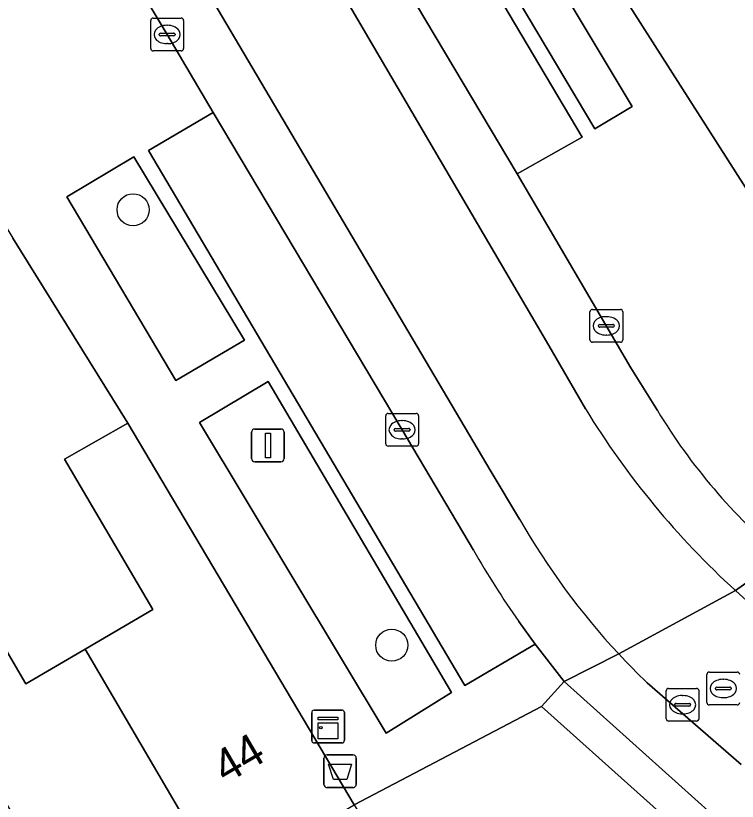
# Model space of a CAD drawing. Extents: x 161771 to 163125, y 382475 to 383179.
# Drawn here: x 162324.43 to 162346.44, y 382872.2 to 382896.16 of the extents above; entities that cross this region are included whole.
import ezdxf

# ---------------------------------------------------------------- set-up
doc = ezdxf.new("R2010")
doc.units = 0
for name, color, linetype in [('IMGEO_Afvalbak', 7, 'Continuous'), ('IMGEO_Boom', 7, 'Continuous'), ('IMGEO_Erf', 7, 'Continuous'), ('IMGEO_Groenvoorziening', 7, 'Continuous'), ('IMGEO_Kast', 7, 'Continuous'), ('IMGEO_Kolk', 7, 'Continuous'), ('IMGEO_Lichtmast', 7, 'Continuous'), ('IMGEO_Pand', 7, 'Continuous'), ('IMGEO_Pand_nummerreeks', 7, 'Continuous'), ('IMGEO_Parkeervlak_open', 7, 'Continuous'), ('IMGEO_Rijbaan_lokaal_gesloten', 7, 'Continuous'), ('IMGEO_Rioolput', 7, 'Continuous'), ('IMGEO_Voetpad_open', 7, 'Continuous')]:
    doc.layers.add(name, color=color, linetype=linetype)

msp = doc.modelspace()

# ---------------------------------------------------------------- linework, layer by layer
at = {"layer": 'IMGEO_Afvalbak'}
for p, q in [((162333.826, 382872.712), (162333.826, 382873.512)), ((162333.826, 382873.512), (162333.826, 382872.712)), ((162333.926, 382873.612), (162334.716, 382873.612)), ((162334.716, 382873.612), (162333.926, 382873.612)), ((162334.816, 382873.512), (162334.816, 382872.712)), ((162334.816, 382872.712), (162334.816, 382873.512)), ((162334.716, 382872.612), (162333.926, 382872.612)), ((162333.926, 382872.612), (162334.716, 382872.612))]:
    msp.add_line(p, q, dxfattribs=at)
msp.add_lwpolyline([(162333.969, 382873.326), (162334.673, 382873.326), (162334.524, 382872.856), (162334.118, 382872.856), (162333.969, 382873.326)], dxfattribs=at)
for centre, start, end in [((162333.926, 382873.512), 90, 180), ((162333.926, 382873.512), 90, 180), ((162334.716, 382873.512), 0, 90), ((162334.716, 382873.512), 360, 90), ((162333.926, 382872.712), 180, 270), ((162333.926, 382872.712), 180, 270), ((162334.716, 382872.712), 270, 0), ((162334.716, 382872.712), 270, 0)]:
    msp.add_arc(centre, 0.1, start, end, dxfattribs=at)
at = {"layer": 'IMGEO_Boom'}
for centre in [(162328.009, 382890.24), (162335.898, 382876.956)]:
    msp.add_circle(centre, 0.489, dxfattribs=at)
at = {"layer": 'IMGEO_Erf'}
for points in [[(162282.694, 382998.745), (162285.645, 382993.994), (162299.205, 382971.267), (162304.602, 382962.221), (162323.715, 382930.187), (162324.058, 382929.531), (162333.904, 382911.866), (162340.209, 382901.345), (162341.191, 382899.707), (162342.707, 382897.177), (162347.841, 382889.118), (162350.419, 382884.987), (162352.762, 382884.507), (162396.81, 382874.496)], [(162321.996, 382880.467), (162324.742, 382875.779), (162326.547, 382876.836), (162328.611, 382878.045), (162325.922, 382882.636), (162327.846, 382883.731), (162324.342, 382889.373)]]:
    msp.add_lwpolyline(points, dxfattribs=at)
at = {"layer": 'IMGEO_Groenvoorziening'}
for points in [[(162337.338, 382903.237), (162336.212, 382902.585), (162342.088, 382892.713), (162343.227, 382893.391)], [(162325.987, 382890.634), (162329.311, 382885.035), (162331.402, 382886.259), (162328.034, 382891.856)], [(162337.722, 382875.511), (162332.133, 382884.998), (162330.03, 382883.755), (162335.725, 382874.269)]]:
    msp.add_lwpolyline(points, close=True, dxfattribs=at)
at = {"layer": 'IMGEO_Kast'}
for p, q in [((162333.456, 382874.05), (162333.456, 382874.891)), ((162333.456, 382874.891), (162333.456, 382874.05)), ((162333.531, 382874.975), (162334.372, 382874.975)), ((162334.372, 382874.975), (162333.531, 382874.975)), ((162334.456, 382874.9), (162334.456, 382874.059)), ((162334.456, 382874.059), (162334.456, 382874.9)), ((162334.381, 382873.975), (162333.54, 382873.975)), ((162333.54, 382873.975), (162334.381, 382873.975))]:
    msp.add_line(p, q, dxfattribs=at)
for points in [[(162333.651, 382874.765), (162334.251, 382874.765), (162334.251, 382874.68), (162333.651, 382874.68), (162333.651, 382874.765)], [(162333.651, 382874.59), (162334.251, 382874.59), (162334.251, 382874.101), (162333.651, 382874.101), (162333.651, 382874.59)]]:
    msp.add_lwpolyline(points, dxfattribs=at)
msp.add_circle((162333.735, 382874.439), 0.0377, dxfattribs=at)
for centre, start, end in [((162333.534, 382874.897), 92.4484, 184.2845), ((162333.534, 382874.897), 92.4484, 184.2845), ((162334.378, 382874.897), 2.4484, 94.2845), ((162334.378, 382874.897), 2.4484, 94.2845), ((162333.534, 382874.053), 182.4484, 274.2845), ((162333.534, 382874.053), 182.4484, 274.2845), ((162334.378, 382874.053), 272.4484, 4.2845), ((162334.378, 382874.053), 272.4484, 4.2845)]:
    msp.add_arc(centre, 0.0779, start, end, dxfattribs=at)
at = {"layer": 'IMGEO_Kolk'}
for p, q in [((162328.547, 382895.161), (162328.547, 382896.013)), ((162328.622, 382896.087), (162329.474, 382896.087)), ((162329.548, 382896.013), (162329.548, 382895.161)), ((162329.035, 382895.867), (162329.06, 382895.867)), ((162328.806, 382895.581), (162328.806, 382895.593)), ((162329.244, 382895.544), (162328.846, 382895.544)), ((162328.849, 382895.63), (162329.247, 382895.63)), ((162329.29, 382895.593), (162329.29, 382895.581)), ((162329.058, 382895.307), (162329.033, 382895.307)), ((162329.474, 382895.087), (162328.622, 382895.087)), ((162341.943, 382886.273), (162341.943, 382887.125)), ((162342.018, 382887.199), (162342.87, 382887.199)), ((162342.944, 382887.125), (162342.944, 382886.273)), ((162342.431, 382886.979), (162342.456, 382886.979)), ((162342.202, 382886.693), (162342.202, 382886.705)), ((162342.64, 382886.656), (162342.242, 382886.656)), ((162342.245, 382886.742), (162342.643, 382886.742)), ((162342.686, 382886.705), (162342.686, 382886.693)), ((162342.454, 382886.419), (162342.429, 382886.419)), ((162342.87, 382886.199), (162342.018, 382886.199)), ((162335.789, 382884.028), (162336.641, 382884.028)), ((162335.714, 382883.102), (162335.714, 382883.954)), ((162336.202, 382883.808), (162336.227, 382883.808)), ((162336.715, 382883.954), (162336.715, 382883.102)), ((162335.973, 382883.522), (162335.973, 382883.534)), ((162336.016, 382883.571), (162336.414, 382883.571)), ((162336.457, 382883.534), (162336.457, 382883.522)), ((162336.411, 382883.485), (162336.013, 382883.485)), ((162336.641, 382883.028), (162335.789, 382883.028)), ((162336.225, 382883.248), (162336.2, 382883.248))]:
    msp.add_line(p, q, dxfattribs=at)
for points in [[(162328.547, 382895.161), (162328.547, 382896.013)], [(162328.622, 382896.087), (162329.474, 382896.087)], [(162329.548, 382896.013), (162329.548, 382895.161)], [(162329.474, 382895.087), (162328.622, 382895.087)], [(162341.943, 382886.273), (162341.943, 382887.125)], [(162342.018, 382887.199), (162342.87, 382887.199)], [(162342.944, 382887.125), (162342.944, 382886.273)], [(162342.87, 382886.199), (162342.018, 382886.199)], [(162335.789, 382884.028), (162336.641, 382884.028)], [(162335.714, 382883.102), (162335.714, 382883.954)], [(162336.715, 382883.954), (162336.715, 382883.102)], [(162336.641, 382883.028), (162335.789, 382883.028)]]:
    msp.add_lwpolyline(points, dxfattribs=at)
for centre, radius, start, end in [((162328.624, 382896.011), 0.0765, 91.552, 178.448), ((162328.624, 382896.011), 0.0765, 91.552, 178.448), ((162329.472, 382896.011), 0.0765, 1.552, 88.448), ((162329.472, 382896.011), 0.0765, 1.552, 88.448), ((162328.846, 382895.59), 0.0403, 85.8775, 175.7526), ((162328.843, 382895.58), 0.0366, 178.938, 274.7102), ((162329.247, 382895.587), 0.043, 264.8664, 352.4533), ((162329.251, 382895.592), 0.0386, 1.7309, 96.639), ((162328.624, 382895.163), 0.0765, 181.552, 268.448), ((162328.624, 382895.163), 0.0765, 181.552, 268.448), ((162329.472, 382895.163), 0.0765, 271.552, 358.448), ((162329.472, 382895.163), 0.0765, 271.552, 358.448), ((162342.02, 382887.123), 0.0765, 91.552, 178.448), ((162342.02, 382887.123), 0.0765, 91.552, 178.448), ((162342.868, 382887.123), 0.0765, 1.552, 88.448), ((162342.868, 382887.123), 0.0765, 1.552, 88.448), ((162342.242, 382886.702), 0.0403, 85.8775, 175.7526), ((162342.239, 382886.692), 0.0366, 178.938, 274.7102), ((162342.643, 382886.699), 0.043, 264.8664, 352.4533), ((162342.647, 382886.704), 0.0386, 1.7309, 96.639), ((162342.02, 382886.275), 0.0765, 181.552, 268.448), ((162342.02, 382886.275), 0.0765, 181.552, 268.448), ((162342.868, 382886.275), 0.0765, 271.552, 358.448), ((162342.868, 382886.275), 0.0765, 271.552, 358.448), ((162335.791, 382883.952), 0.0765, 91.552, 178.448), ((162335.791, 382883.952), 0.0765, 91.552, 178.448), ((162336.639, 382883.952), 0.0765, 1.552, 88.448), ((162336.639, 382883.952), 0.0765, 1.552, 88.448), ((162336.013, 382883.531), 0.0403, 85.8775, 175.7526), ((162336.01, 382883.521), 0.0366, 178.938, 274.7102), ((162336.414, 382883.528), 0.043, 264.8664, 352.4533), ((162336.418, 382883.533), 0.0386, 1.7309, 96.639), ((162335.791, 382883.104), 0.0765, 181.552, 268.448), ((162335.791, 382883.104), 0.0765, 181.552, 268.448), ((162336.639, 382883.104), 0.0765, 271.552, 358.448), ((162336.639, 382883.104), 0.0765, 271.552, 358.448)]:
    msp.add_arc(centre, radius, start, end, dxfattribs=at)
for centre, major_axis, ratio, start_param, end_param in [((162329.034, 382895.587), (-0.387, 0.002), 0.722429, 4.712389, 7.853982), ((162329.059, 382895.587), (-0.39, 0.002), 0.717154, 1.570796, 4.712389), ((162342.43, 382886.699), (-0.387, 0.002), 0.722429, 4.712389, 7.853982), ((162342.455, 382886.699), (-0.39, 0.002), 0.717154, 1.570796, 4.712389), ((162336.201, 382883.528), (-0.387, 0.002), 0.722429, 4.712389, 7.853982), ((162336.226, 382883.528), (-0.39, 0.002), 0.717154, 1.570796, 4.712389)]:
    msp.add_ellipse(centre, major_axis=major_axis, ratio=ratio, start_param=start_param, end_param=end_param, dxfattribs=at)
at = {"layer": 'IMGEO_Lichtmast'}
for p, q in [((162331.725, 382883.552), (162332.515, 382883.552)), ((162332.515, 382883.552), (162331.725, 382883.552)), ((162331.625, 382882.652), (162331.625, 382883.452)), ((162331.625, 382883.452), (162331.625, 382882.652)), ((162332.615, 382883.452), (162332.615, 382882.652)), ((162332.615, 382882.652), (162332.615, 382883.452)), ((162332.515, 382882.552), (162331.725, 382882.552)), ((162331.725, 382882.552), (162332.515, 382882.552))]:
    msp.add_line(p, q, dxfattribs=at)
msp.add_lwpolyline([(162332.045, 382883.427), (162332.195, 382883.427), (162332.195, 382882.677), (162332.045, 382882.677), (162332.045, 382883.427)], dxfattribs=at)
for centre, start, end in [((162331.725, 382883.452), 90, 180), ((162331.725, 382883.452), 90, 180), ((162332.515, 382883.452), 0, 90), ((162332.515, 382883.452), 360, 90), ((162331.725, 382882.652), 180, 270), ((162331.725, 382882.652), 180, 270), ((162332.515, 382882.652), 270, 0), ((162332.515, 382882.652), 270, 0)]:
    msp.add_arc(centre, 0.1, start, end, dxfattribs=at)
at = {"layer": 'IMGEO_Pand'}
for points in [[(162326.547, 382876.836), (162330.715, 382869.722), (162334.753, 382872.09), (162327.846, 382883.731), (162325.922, 382882.636), (162328.611, 382878.045)], [(162326.547, 382876.836), (162324.742, 382875.779), (162321.996, 382880.467), (162319.943, 382879.265), (162326.87, 382867.467), (162330.715, 382869.722)]]:
    msp.add_lwpolyline(points, close=True, dxfattribs=at)
at = {"layer": 'IMGEO_Parkeervlak_open'}
msp.add_lwpolyline([(162324.516, 382916.948), (162326.603, 382913.414), (162335.002, 382899.266), (162339.727, 382891.336), (162341.708, 382892.457), (162326.472, 382918.127)], close=True, dxfattribs=at)
for points in [[(162330.45, 382893.21), (162328.48, 382892.052), (162338.126, 382875.73), (162340.269, 382876.989), (162339.771, 382877.679)], [(162338.393, 382879.852), (162336.215, 382883.528), (162330.45, 382893.21)]]:
    msp.add_lwpolyline(points, dxfattribs=at)
msp.add_arc((162363.534, 382894.272), 28.983, 209.8365, 214.9249, dxfattribs=at)
at = {"layer": 'IMGEO_Rijbaan_lokaal_gesloten'}
for points in [[(162252.687, 383027.32), (162258.27, 383017.942), (162277.114, 382986.385), (162314.204, 382923.986), (162330.304, 382896.843), (162338.934, 382882.25), (162339.793, 382880.803)], [(162341.807, 382884.166), (162340.693, 382886.098), (162333.368, 382898.598), (162322.883, 382916.238), (162309.554, 382938.696), (162306.687, 382943.516), (162275.079, 382996.8)], [(162275.079, 382996.8), (162306.687, 382943.516), (162309.554, 382938.696), (162322.883, 382916.238), (162333.368, 382898.598), (162340.693, 382886.098), (162341.807, 382884.166)], [(162344.002, 382884.116), (162343.193, 382885.422), (162339.727, 382891.336), (162335.002, 382899.266), (162326.603, 382913.414), (162324.516, 382916.948), (162318.235, 382927.528), (162317.64, 382928.532), (162316.912, 382929.741), (162308.432, 382943.993), (162300.77, 382956.887), (162300.224, 382957.807), (162293.232, 382969.581), (162288.514, 382977.525), (162281.441, 382989.446), (162278.279, 382994.741), (162277.713, 382995.702)], [(162339.793, 382880.803), (162338.934, 382882.25), (162330.304, 382896.843), (162314.204, 382923.986), (162277.114, 382986.385)], [(162295.546, 382952.022), (162297.385, 382948.927), (162297.447, 382948.823), (162302.486, 382940.342), (162311.925, 382924.471), (162312.752, 382923.086), (162312.819, 382922.973), (162314.64, 382919.896), (162317.99, 382914.237), (162320.653, 382909.74), (162327.107, 382898.845), (162329.048, 382895.587), (162330.45, 382893.21), (162336.215, 382883.528), (162338.393, 382879.852)], [(162346.383, 382878.623), (162347.819, 382879.644)], [(162347.819, 382879.644), (162346.383, 382878.623)], [(162342.821, 382876.69), (162346.383, 382878.623)], [(162346.383, 382878.623), (162342.821, 382876.69)], [(162339.771, 382877.679), (162340.269, 382876.989), (162341.158, 382875.854), (162342.821, 382876.69)], [(162342.821, 382876.69), (162341.158, 382875.854), (162345.639, 382871.819)], [(162343.684, 382875.811), (162346.554, 382873.321)], [(162346.554, 382873.321), (162343.684, 382875.811)]]:
    msp.add_lwpolyline(points, dxfattribs=at)
for centre, radius, start, end in [((162363.558, 382897.462), 25.493, 211.4368, 227.6457), ((162363.558, 382897.462), 25.493, 211.4368, 227.6457), ((162359.448, 382893.434), 18.039, 211.1026, 229.8611), ((162359.274, 382891.974), 22.457, 209.8311, 222.8901), ((162359.274, 382891.974), 22.457, 209.8311, 222.8901), ((162363.534, 382894.272), 28.983, 209.8365, 214.9249), ((162363.548, 382897.452), 25.479, 227.6459, 260.8098), ((162363.548, 382897.452), 25.479, 227.6459, 260.8098), ((162359.189, 382891.897), 22.342, 222.894, 226.0535), ((162359.189, 382891.897), 22.342, 222.894, 226.0535)]:
    msp.add_arc(centre, radius, start, end, dxfattribs=at)
at = {"layer": 'IMGEO_Rioolput'}
for p, q in [((162345.585, 382876.136), (162346.437, 382876.136)), ((162345.51, 382875.21), (162345.51, 382876.062)), ((162345.998, 382875.916), (162346.023, 382875.916)), ((162344.343, 382875.64), (162345.195, 382875.64)), ((162345.769, 382875.63), (162345.769, 382875.642)), ((162346.207, 382875.593), (162345.809, 382875.593)), ((162345.812, 382875.679), (162346.21, 382875.679)), ((162346.253, 382875.642), (162346.253, 382875.63)), ((162344.268, 382874.714), (162344.268, 382875.566)), ((162344.756, 382875.42), (162344.781, 382875.42)), ((162345.269, 382875.566), (162345.269, 382874.714)), ((162346.021, 382875.356), (162345.996, 382875.356)), ((162344.527, 382875.134), (162344.527, 382875.146)), ((162344.57, 382875.183), (162344.968, 382875.183)), ((162345.011, 382875.146), (162345.011, 382875.134)), ((162346.437, 382875.136), (162345.585, 382875.136)), ((162344.965, 382875.097), (162344.567, 382875.097)), ((162345.195, 382874.64), (162344.343, 382874.64)), ((162344.779, 382874.86), (162344.754, 382874.86))]:
    msp.add_line(p, q, dxfattribs=at)
for points in [[(162345.585, 382876.136), (162346.437, 382876.136)], [(162345.51, 382875.21), (162345.51, 382876.062)], [(162344.343, 382875.64), (162345.195, 382875.64)], [(162344.268, 382874.714), (162344.268, 382875.566)], [(162345.269, 382875.566), (162345.269, 382874.714)], [(162346.437, 382875.136), (162345.585, 382875.136)], [(162345.195, 382874.64), (162344.343, 382874.64)]]:
    msp.add_lwpolyline(points, dxfattribs=at)
for centre, radius, start, end in [((162345.587, 382876.06), 0.0765, 91.552, 178.448), ((162345.587, 382876.06), 0.0765, 91.552, 178.448), ((162346.435, 382876.06), 0.0765, 1.552, 88.448), ((162346.435, 382876.06), 0.0765, 1.552, 88.448), ((162344.345, 382875.564), 0.0765, 91.552, 178.448), ((162344.345, 382875.564), 0.0765, 91.552, 178.448), ((162345.193, 382875.564), 0.0765, 1.552, 88.448), ((162345.193, 382875.564), 0.0765, 1.552, 88.448), ((162345.809, 382875.639), 0.0403, 85.8775, 175.7526), ((162345.806, 382875.629), 0.0366, 178.938, 274.7102), ((162346.21, 382875.636), 0.043, 264.8664, 352.4533), ((162346.214, 382875.641), 0.0386, 1.7309, 96.639), ((162344.567, 382875.143), 0.0403, 85.8775, 175.7526), ((162344.564, 382875.133), 0.0366, 178.938, 274.7102), ((162344.968, 382875.14), 0.043, 264.8664, 352.4533), ((162344.972, 382875.145), 0.0386, 1.7309, 96.639), ((162345.587, 382875.212), 0.0765, 181.552, 268.448), ((162345.587, 382875.212), 0.0765, 181.552, 268.448), ((162346.435, 382875.212), 0.0765, 271.552, 358.448), ((162346.435, 382875.212), 0.0765, 271.552, 358.448), ((162344.345, 382874.716), 0.0765, 181.552, 268.448), ((162344.345, 382874.716), 0.0765, 181.552, 268.448), ((162345.193, 382874.716), 0.0765, 271.552, 358.448), ((162345.193, 382874.716), 0.0765, 271.552, 358.448)]:
    msp.add_arc(centre, radius, start, end, dxfattribs=at)
for centre, major_axis, ratio, start_param, end_param in [((162345.997, 382875.636), (-0.387, 0.002), 0.722429, 4.712389, 7.853982), ((162346.022, 382875.636), (-0.39, 0.002), 0.717154, 1.570796, 4.712389), ((162344.755, 382875.14), (-0.387, 0.002), 0.722429, 4.712389, 7.853982), ((162344.78, 382875.14), (-0.39, 0.002), 0.717154, 1.570796, 4.712389)]:
    msp.add_ellipse(centre, major_axis=major_axis, ratio=ratio, start_param=start_param, end_param=end_param, dxfattribs=at)
at = {"layer": 'IMGEO_Voetpad_open'}
for points in [[(162298.198, 382970.688), (162299.205, 382971.267), (162285.645, 382993.994), (162282.694, 382998.745), (162282.561, 382998.663), (162282.621, 382998.564), (162281.332, 382997.822), (162277.713, 382995.702), (162278.279, 382994.741), (162281.441, 382989.446), (162283.412, 382990.65), (162295.219, 382970.753), (162293.232, 382969.581), (162300.224, 382957.807), (162302.215, 382959.014), (162320.137, 382928.801), (162318.235, 382927.528), (162324.516, 382916.948), (162326.472, 382918.127), (162341.708, 382892.457), (162339.727, 382891.336), (162343.193, 382885.422), (162344.002, 382884.116)], [(162350.419, 382884.987), (162347.841, 382889.118), (162342.707, 382897.177), (162341.191, 382899.707), (162340.209, 382901.345), (162333.904, 382911.866), (162324.058, 382929.531), (162323.715, 382930.187), (162304.602, 382962.221), (162303.031, 382961.271)], [(162319.458, 382898.268), (162321.256, 382895.257), (162321.819, 382894.324), (162321.477, 382894.129), (162324.342, 382889.373), (162327.846, 382883.731), (162334.753, 382872.09), (162340.467, 382875.088), (162341.158, 382875.854), (162340.269, 382876.989), (162338.126, 382875.73), (162328.48, 382892.052), (162330.45, 382893.21), (162329.048, 382895.587), (162327.107, 382898.845)], [(162345.639, 382871.819), (162344.935, 382871.078), (162340.467, 382875.088), (162334.753, 382872.09), (162337.996, 382866.606), (162337.922, 382866.562), (162339.695, 382863.55), (162340.118, 382862.752), (162361.719, 382857.866), (162366.267, 382856.68)]]:
    msp.add_lwpolyline(points, dxfattribs=at)
for points in [[(162336.212, 382902.585), (162337.338, 382903.237), (162343.227, 382893.391), (162342.088, 382892.713)], [(162328.034, 382891.856), (162331.402, 382886.259), (162329.311, 382885.035), (162325.987, 382890.634)], [(162332.133, 382884.998), (162337.722, 382875.511), (162335.725, 382874.269), (162330.03, 382883.755)], [(162341.158, 382875.854), (162340.467, 382875.088), (162344.935, 382871.078), (162345.639, 382871.819)]]:
    msp.add_lwpolyline(points, close=True, dxfattribs=at)
msp.add_arc((162359.448, 382893.434), 18.039, 211.1026, 229.8611, dxfattribs=at)

# ---------------------------------------------------------------- texts
at = {"layer": 'IMGEO_Pand_nummerreeks'}
msp.add_text('44', height=1, rotation=30.3874, dxfattribs=at).set_placement((162330.829, 382872.71))

doc.saveas('drawing.dxf')
